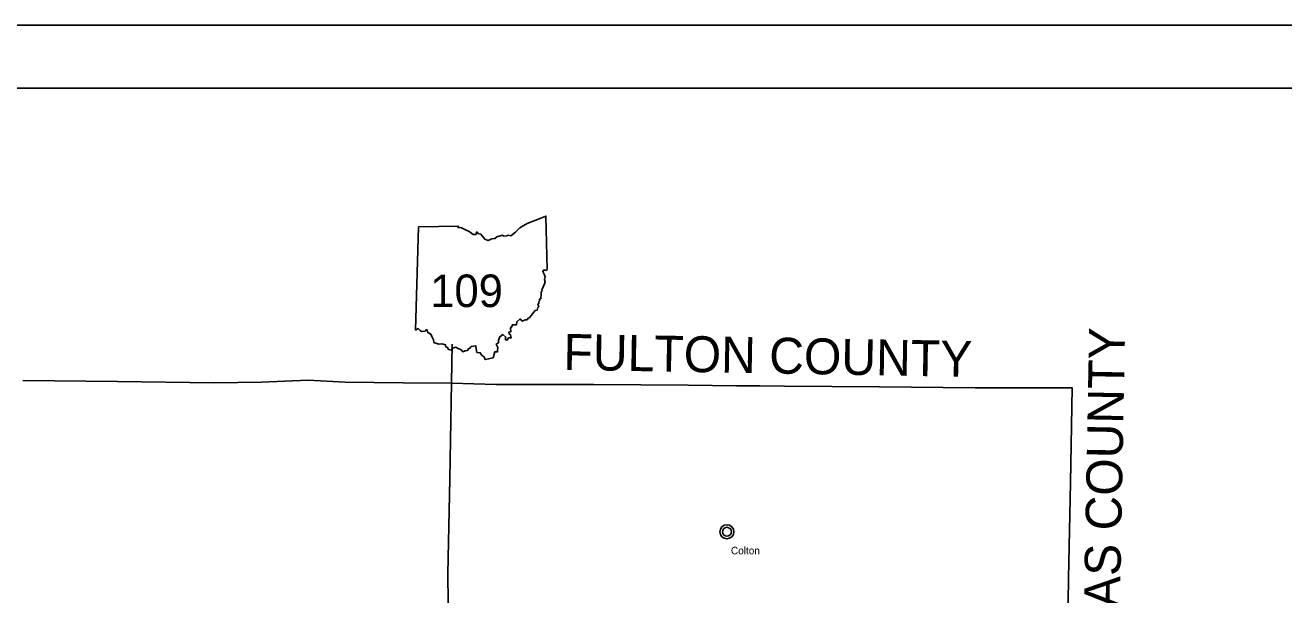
# Model space of a CAD drawing. Extents: x -62 to 810, y 0 to 440.
# Drawn here: x 317.5 to 517, y 349.6 to 440 of the extents above; entities that cross this region are included whole.
import ezdxf

# ---------------------------------------------------------------- set-up
doc = ezdxf.new("R2010")
doc.units = 0
for name, color, linetype in [('DV_X_Corp_Line', 7, 'Continuous'), ('GM_X_Adjacent_County_Text', 7, 'Continuous'), ('GM_X_Corporation_Text', 7, 'Continuous'), ('GM_X_County', 7, 'Continuous'), ('GM_X_State_Route', 7, 'Continuous'), ('PV_P_Text', 7, 'Continuous'), ('SH_Border', 7, 'Continuous'), ('SH_Cut_Line', 7, 'Continuous')]:
    doc.layers.add(name, color=color, linetype=linetype)

msp = doc.modelspace()

# ---------------------------------------------------------------- linework, layer by layer
at = {"layer": 'DV_X_Corp_Line'}
for radius in [1.12, 0.71]:
    msp.add_circle((428.74, 359.63), radius, dxfattribs=at)
at = {"layer": 'GM_X_County'}
msp.add_lwpolyline([(482.76, 344.73), (482.9, 352.28), (483.18, 367.39), (483.46, 382.49), (468.08, 382.47), (452.95, 382.61), (437.85, 382.74), (433.98, 382.78), (430.27, 382.81), (422.62, 382.88), (415.1, 382.94), (407.59, 383.01), (392.76, 382.98), (392.16, 382.98), (385.1, 383.22), (377.45, 383.28), (368.22, 383.36), (362.37, 383.7), (355, 383.38), (347.4, 383.24), (332.13, 383.45), (317.13, 383.65)], dxfattribs=at)
at = {"layer": 'GM_X_State_Route'}
msp.add_lwpolyline([(384.5, 345.37), (384.58, 348.41), (384.53, 352.97), (384.81, 368.02), (385.21, 389.41)], dxfattribs=at)
at = {"layer": 'PV_P_Text'}
msp.add_line((379.38, 391.62), (379.84, 408), dxfattribs=at)
msp.add_line((379.38, 391.62), (379.84, 408), dxfattribs=at)
for points in [[(379.84, 408), (386.2, 408.1), (386.1, 407.91), (386.7, 407.86), (387.33, 407.52), (387.87, 407.29), (388.53, 406.77), (388.92, 406.78), (389.09, 407.21), (389.39, 406.88), (389.75, 406.82), (390.37, 406.03), (390.88, 405.86), (391.49, 406.13), (391.95, 406.18), (392.29, 406.44), (393.16, 406.67), (393.4, 406.53), (393.86, 406.56), (394.09, 406.66), (394.5, 406.57), (395.21, 407.17), (395.93, 407.87), (397.06, 408.53), (398.73, 409.16), (400.06, 409.72), (400.25, 401.22)], [(379.84, 408), (386.2, 408.1), (386.1, 407.91), (386.7, 407.86), (387.33, 407.52), (387.87, 407.29), (388.53, 406.77), (388.92, 406.78), (389.09, 407.21), (389.39, 406.88), (389.75, 406.82), (390.37, 406.03), (390.88, 405.86), (391.49, 406.13), (391.95, 406.18), (392.29, 406.44), (393.16, 406.67), (393.4, 406.53), (393.86, 406.56), (394.09, 406.66), (394.5, 406.57), (395.21, 407.17), (395.93, 407.87), (397.06, 408.53), (398.73, 409.16), (400.06, 409.72), (400.25, 401.22)], [(400.25, 401.22), (400.05, 401.1), (399.75, 401.16), (399.54, 400.92), (399.8, 400.52), (399.92, 400.1), (399.81, 399.64), (399.92, 399.26), (399.84, 398.94), (399.65, 398.62), (399.59, 398.32), (399.42, 398), (399.44, 397.82), (399.28, 397.68), (399.31, 397.15), (399.23, 396.85), (399.26, 396.6), (399.01, 396.53), (399.07, 396.32), (398.91, 396.16), (398.94, 395.88), (398.76, 395.7), (398.94, 395.35), (398.79, 395.23), (398.68, 394.8), (398.35, 394.71), (397.71, 393.92), (397.48, 393.62), (397.22, 393.54), (397.08, 393.24), (396.77, 393.24), (396.29, 393.02), (395.98, 393.39), (395.44, 392.95), (395.38, 392.44), (394.69, 392.45), (394.72, 392.2), (394.57, 392.12), (394.43, 391.86), (394.51, 391.4), (394.19, 391.28), (394.23, 391.02), (394.43, 390.85), (394.53, 390.35), (394.19, 390.45), (393.91, 390.02), (393.62, 390.12), (393.71, 390.48), (393.23, 390.92), (392.77, 390.57), (392.53, 390.01), (392.53, 389.63), (392.19, 389.41), (392.41, 388.87), (392.37, 388.51), (392.38, 388.16), (391.95, 388.17), (391.69, 387.23)], [(400.25, 401.22), (400.05, 401.1), (399.75, 401.16), (399.54, 400.92), (399.8, 400.52), (399.92, 400.1), (399.81, 399.64), (399.92, 399.26), (399.84, 398.94), (399.65, 398.62), (399.59, 398.32), (399.42, 398), (399.44, 397.82), (399.28, 397.68), (399.31, 397.15), (399.23, 396.85), (399.26, 396.6), (399.01, 396.53), (399.07, 396.32), (398.91, 396.16), (398.94, 395.88), (398.76, 395.7), (398.94, 395.35), (398.79, 395.23), (398.68, 394.8), (398.35, 394.71), (397.71, 393.92), (397.48, 393.62), (397.22, 393.54), (397.08, 393.24), (396.77, 393.24), (396.29, 393.02), (395.98, 393.39), (395.44, 392.95), (395.38, 392.44), (394.69, 392.45), (394.72, 392.2), (394.57, 392.12), (394.43, 391.86), (394.51, 391.4), (394.19, 391.28), (394.23, 391.02), (394.43, 390.85), (394.53, 390.35), (394.19, 390.45), (393.91, 390.02), (393.62, 390.12), (393.71, 390.48), (393.23, 390.92), (392.77, 390.57), (392.53, 390.01), (392.53, 389.63), (392.19, 389.41), (392.41, 388.87), (392.37, 388.51), (392.38, 388.16), (391.95, 388.17), (391.69, 387.23)], [(391.69, 387.23), (390.95, 387.05), (390.43, 386.94), (390.25, 387.37), (389.89, 387.6), (389.65, 388.03), (389.12, 388.08), (388.99, 388.67), (388.93, 389.15), (388.21, 389.03), (388.01, 388.74), (387.76, 388.66), (387.61, 388.37), (387.26, 388.34), (386.88, 388.2), (386.64, 388.49), (386.02, 388.78), (385.75, 388.93), (385.17, 388.7), (385.05, 388.43), (384.59, 388.55), (384.48, 388.85), (384.2, 388.95), (384.14, 389.27), (383.55, 389.45), (383.09, 389.38), (382.29, 389.64), (382.24, 390.07), (381.97, 390.59), (381.82, 390.96), (381.32, 391.23), (381.21, 391.66), (381.05, 391.65), (380.9, 391.48), (380.34, 391.4), (380.12, 391.57), (379.8, 391.87), (379.38, 391.62)], [(391.69, 387.23), (390.95, 387.05), (390.43, 386.94), (390.25, 387.37), (389.89, 387.6), (389.65, 388.03), (389.12, 388.08), (388.99, 388.67), (388.93, 389.15), (388.21, 389.03), (388.01, 388.74), (387.76, 388.66), (387.61, 388.37), (387.26, 388.34), (386.88, 388.2), (386.64, 388.49), (386.02, 388.78), (385.75, 388.93), (385.17, 388.7), (385.05, 388.43), (384.59, 388.55), (384.48, 388.85), (384.2, 388.95), (384.14, 389.27), (383.55, 389.45), (383.09, 389.38), (382.29, 389.64), (382.24, 390.07), (381.97, 390.59), (381.82, 390.96), (381.32, 391.23), (381.21, 391.66), (381.05, 391.65), (380.9, 391.48), (380.34, 391.4), (380.12, 391.57), (379.8, 391.87), (379.38, 391.62)]]:
    msp.add_lwpolyline(points, dxfattribs=at)
at = {"layer": 'SH_Border'}
msp.add_lwpolyline([(30, 430), (670, 430), (670, 10), (30, 10)], close=True, dxfattribs=at)
at = {"layer": 'SH_Cut_Line'}
msp.add_lwpolyline([(0, 0), (680, 0), (680, 440), (0, 440)], close=True, dxfattribs=at)

# ---------------------------------------------------------------- texts
at = {"layer": 'GM_X_Adjacent_County_Text'}
for s, rotation, p in [('FULTON COUNTY', 358.9893, (402.8, 385.33)), ('LUCAS COUNTY', 88.9277, (490.74, 332.27))]:
    msp.add_text(s, height=5.7, rotation=rotation, dxfattribs=at).set_placement(p)
at = {"layer": 'GM_X_Corporation_Text'}
msp.add_text('Colton', height=1.188, rotation=0, dxfattribs=at).set_placement((429.38, 356.06))
at = {"layer": 'PV_P_Text'}
msp.add_text('109', height=5.162, dxfattribs=at).set_placement((381.72, 395.28))

doc.saveas('drawing.dxf')
